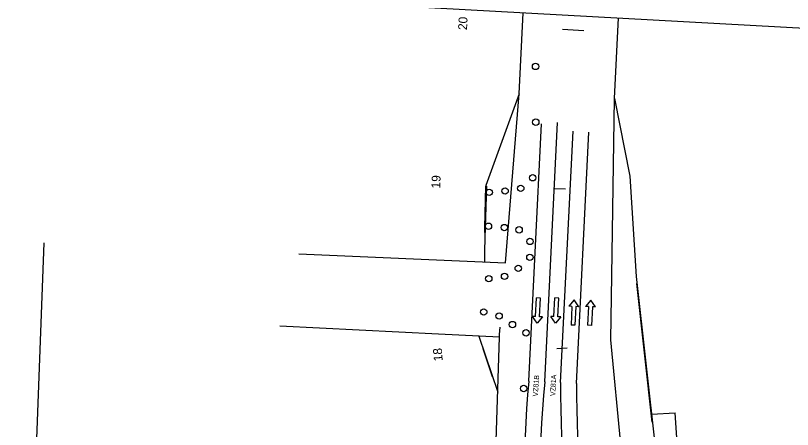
# Model space of a CAD drawing. Extents: x 0 to 1361828, y 0 to 1470398.
# Drawn here: x 685888.8 to 686377.1, y 735099.3 to 735359.4 of the extents above; entities that cross this region are included whole.
import ezdxf

# ---------------------------------------------------------------- set-up
doc = ezdxf.new("R2010")
doc.units = 0
for name, color, linetype in [('$', 7, 'Continuous'), ('border All Plan 20-40 - Level 1', 7, 'Continuous'), ('MOT Stage 1', 7, 'Continuous'), ('MOT Stage 1 Lanes', 7, 'Continuous'), ('R_Horz Alg Station', 7, 'Continuous'), ('R_TYPE_A_CURB', 7, 'Continuous'), ('RW-EX', 7, 'Continuous'), ('RW-PR', 7, 'Continuous'), ('SIGNAL-PR$', 7, 'Continuous')]:
    doc.layers.add(name, color=color, linetype=linetype)

# ---------------------------------------------------------------- blocks, each defined once
blk = doc.blocks.new('BAREL_1801')
at = {"layer": 'MOT Stage 1'}
blk.add_circle((0, 0.01), 2.88, dxfattribs=at)
blk = doc.blocks.new('BAREL_1802')
at = {"layer": 'MOT Stage 1'}
blk.add_circle((0, 0.01), 2.88, dxfattribs=at)
blk = doc.blocks.new('BAREL_1803')
at = {"layer": 'MOT Stage 1'}
blk.add_circle((0, 0.01), 2.88, dxfattribs=at)
blk = doc.blocks.new('BAREL_1804')
at = {"layer": 'MOT Stage 1'}
blk.add_circle((0, 0.01), 2.88, dxfattribs=at)
blk = doc.blocks.new('BAREL_1805')
at = {"layer": 'MOT Stage 1'}
blk.add_circle((0, 0.01), 2.88, dxfattribs=at)
blk = doc.blocks.new('BAREL_1806')
at = {"layer": 'MOT Stage 1'}
blk.add_circle((0, 0.01), 2.88, dxfattribs=at)
blk = doc.blocks.new('BAREL_1842')
at = {"layer": 'MOT Stage 1'}
blk.add_circle((0, 0.01), 2.88, dxfattribs=at)
blk = doc.blocks.new('BAREL_1843')
at = {"layer": 'MOT Stage 1'}
blk.add_circle((0, 0.01), 2.88, dxfattribs=at)
blk = doc.blocks.new('BAREL_1844')
at = {"layer": 'MOT Stage 1'}
blk.add_circle((0, 0.01), 2.88, dxfattribs=at)
blk = doc.blocks.new('BAREL_1845')
at = {"layer": 'MOT Stage 1'}
blk.add_circle((0, 0.01), 2.88, dxfattribs=at)
blk = doc.blocks.new('BAREL_1846')
at = {"layer": 'MOT Stage 1'}
blk.add_circle((0, 0.01), 2.88, dxfattribs=at)
blk = doc.blocks.new('BAREL_1847')
at = {"layer": 'MOT Stage 1'}
blk.add_circle((0, 0.01), 2.88, dxfattribs=at)
blk = doc.blocks.new('BAREL_1848')
at = {"layer": 'MOT Stage 1'}
blk.add_circle((0, 0.01), 2.88, dxfattribs=at)
blk = doc.blocks.new('BAREL_1849')
at = {"layer": 'MOT Stage 1'}
blk.add_circle((0, 0.01), 2.88, dxfattribs=at)
blk = doc.blocks.new('BAREL_1850')
at = {"layer": 'MOT Stage 1'}
blk.add_circle((0, 0.01), 2.88, dxfattribs=at)
blk = doc.blocks.new('BAREL_1851')
at = {"layer": 'MOT Stage 1'}
blk.add_circle((0, 0.01), 2.88, dxfattribs=at)
blk = doc.blocks.new('BAREL_1852')
at = {"layer": 'MOT Stage 1'}
blk.add_circle((0, 0.01), 2.88, dxfattribs=at)
blk = doc.blocks.new('SARROW_225')
at = {"layer": 'MOT Stage 1'}
for p, q in [((-6, -29.4), (-6, 0)), ((0, 0), (-6, 0)), ((0, -29.4), (0, 0)), ((-6, -29.4), (-11, -29.4)), ((-3, -39.8), (-11, -29.4)), ((5, -29.4), (-3, -39.8)), ((5, -29.4), (0, -29.4))]:
    blk.add_line(p, q, dxfattribs=at)
blk = doc.blocks.new('SARROW_226')
at = {"layer": 'MOT Stage 1'}
for p, q in [((-6, -29.4), (-6, 0)), ((0, 0), (-6, 0)), ((0, -29.4), (0, 0)), ((-6, -29.4), (-11, -29.4)), ((-3, -39.8), (-11, -29.4)), ((5, -29.4), (-3, -39.8)), ((5, -29.4), (0, -29.4))]:
    blk.add_line(p, q, dxfattribs=at)
blk = doc.blocks.new('SARROW_227')
at = {"layer": 'MOT Stage 1'}
for p, q in [((-6, -29.4), (-6, 0)), ((0, 0), (-6, 0)), ((0, -29.4), (0, 0)), ((-6, -29.4), (-11, -29.4)), ((-3, -39.8), (-11, -29.4)), ((5, -29.4), (-3, -39.8)), ((5, -29.4), (0, -29.4))]:
    blk.add_line(p, q, dxfattribs=at)
blk = doc.blocks.new('BAREL_1870')
at = {"layer": 'MOT Stage 1'}
blk.add_circle((0, 0.01), 2.88, dxfattribs=at)
blk = doc.blocks.new('BAREL_1871')
at = {"layer": 'MOT Stage 1'}
blk.add_circle((0, 0.01), 2.88, dxfattribs=at)
blk = doc.blocks.new('SARROW_228')
at = {"layer": 'MOT Stage 1'}
for p, q in [((-6, -29.4), (-6, 0)), ((0, 0), (-6, 0)), ((0, -29.4), (0, 0)), ((-6, -29.4), (-11, -29.4)), ((-3, -39.8), (-11, -29.4)), ((5, -29.4), (-3, -39.8)), ((5, -29.4), (0, -29.4))]:
    blk.add_line(p, q, dxfattribs=at)

msp = doc.modelspace()

# ---------------------------------------------------------------- linework, layer by layer
at = {"layer": 'border All Plan 20-40 - Level 1'}
msp.add_line((685446.82, 735403.36), (687025.3, 735315.9), dxfattribs=at)
at = {"layer": 'MOT Stage 1 Lanes'}
for points in [[(686221.44, 735129.26), (686229.44, 735292.13)], [(686211.45, 735129.75), (686219.39, 735291.41)], [(686231.42, 735128.77), (686239.18, 735286.65)], [(686241.41, 735128.27), (686249.17, 735286.16)]]:
    msp.add_lwpolyline(points, dxfattribs=at)
for centre, radius, start, end in [((686946.79, 735060.88), 738.56, 174.64944, 185.44699), ((686946.77, 735060.88), 728.55, 174.61469, 185.41281), ((686944.02, 735124.57), 712.61, 179.66251, 190.45935), ((686944, 735124.56), 702.6, 179.69727, 190.49468)]:
    msp.add_arc(centre, radius, start, end, dxfattribs=at)
at = {"layer": 'R_Horz Alg Station'}
for points in [[(686232.65, 735350.71), (686245.97, 735350.05)], [(686227.77, 735250.77), (686234.43, 735250.5)], [(686228.92, 735150.13), (686235.58, 735150.55)]]:
    msp.add_lwpolyline(points, dxfattribs=at)
at = {"layer": 'R_TYPE_A_CURB'}
for p, q in [((686184.46, 735252.11), (686184.96, 735252.1)), ((686183.73, 735223.02), (686184.23, 735223.01))]:
    msp.add_line(p, q, dxfattribs=at)
for points in [[(686183.73, 735223.02), (686183.74, 735226.25), (686184.46, 735252.11)], [(686184.23, 735223.01), (686184.24, 735226.24), (686184.96, 735252.1)], [(686289.03, 735103.92), (686279.27, 735191.01)], [(686188.63, 735132.43), (686182.76, 735149.94)]]:
    msp.add_lwpolyline(points, dxfattribs=at)
at = {"layer": 'RW-EX'}
for p, q in [((685894.65, 734899.71), (685906.88, 735216.51)), ((686066.93, 735209.73), (686196.68, 735203.99)), ((686282.11, 734952.68), (686263.01, 735155.56))]:
    msp.add_line(p, q, dxfattribs=at)
for points in [[(686196.68, 735203.99), (686205.39, 735310.21), (686207.85, 735361.16)], [(686263.01, 735155.56), (686263.62, 735196.09), (686265.32, 735307.32), (686267.76, 735357.83)], [(686193.04, 735157.41), (686154.73, 735159.27), (686054.94, 735164.12)], [(686189.41, 735046.56), (686193.04, 735157.41), (686193.09, 735158.93), (686193.31, 735163.53)]]:
    msp.add_lwpolyline(points, dxfattribs=at)
at = {"layer": 'RW-PR'}
for p, q in [((686180.05, 735158.04), (686191.9, 735122.66)), ((686288.47, 735108.89), (686303.36, 735109.86)), ((686306.92, 735054.97), (686303.36, 735109.86))]:
    msp.add_line(p, q, dxfattribs=at)
for points in [[(686205.39, 735310.21), (686184.48, 735252.55), (686183.74, 735226.25), (686183.66, 735204.57)], [(686265.32, 735307.32), (686274.84, 735258.53), (686278.78, 735195.38), (686290.99, 735086.46), (686300.18, 735004.43), (686311.76, 734922.2), (686343.56, 734897.83)]]:
    msp.add_lwpolyline(points, dxfattribs=at)

# ---------------------------------------------------------------- block references
at = {"layer": 'MOT Stage 1'}
for name, p, xscale, yscale, rotation in [('BAREL_1871', (686215.66, 735327.39), 0.6945420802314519, 0.6945420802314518, 87.04179557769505), ('BAREL_1870', (686215.8, 735292.39), 0.6945420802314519, 0.6945420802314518, 87.04179557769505), ('BAREL_1852', (686213.86, 735257.45), 0.6945420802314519, 0.6945420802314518, 87.04179557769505), ('BAREL_1851', (686206.34, 735250.85), 0.6945420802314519, 0.6945420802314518, 87.04179557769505), ('BAREL_1803', (686186.53, 735248.3), 0.6945420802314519, 0.6945420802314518, 87.04179557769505), ('BAREL_1850', (686196.5, 735249.11), 0.6945420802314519, 0.6945420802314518, 87.04179557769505), ('BAREL_1804', (686186.07, 735226.99), 0.6945420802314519, 0.6945420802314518, 87.04179557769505), ('BAREL_1805', (686196.03, 735226.18), 0.6945420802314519, 0.6945420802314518, 87.04179557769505), ('BAREL_1806', (686205.33, 735224.75), 0.6945420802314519, 0.6945420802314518, 87.04179557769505), ('BAREL_1845', (686212.15, 735217.43), 0.6945420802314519, 0.6945420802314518, 87.04179557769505), ('BAREL_1846', (686212.07, 735207.43), 0.6945420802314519, 0.6945420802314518, 87.04179557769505), ('BAREL_1847', (686204.78, 735200.59), 0.6945420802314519, 0.6945420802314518, 87.04179557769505), ('BAREL_1849', (686186.27, 735194.04), 0.6945420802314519, 0.6945420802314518, 87.04179557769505), ('BAREL_1848', (686196.16, 735195.52), 0.6945420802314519, 0.6945420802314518, 87.04179557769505), ('SARROW_225', (686218.68, 735181.91), 0.4000000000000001, 0.4000000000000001, -2.7722917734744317), ('SARROW_228', (686230.18, 735181.91), 0.4000000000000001, 0.4000000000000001, -2.7722917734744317), ('SARROW_226', (686240.32, 735164.82), 0.39999999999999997, -0.4, -2.7722917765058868), ('SARROW_227', (686250.79, 735164.63), 0.39999999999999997, -0.4, -2.7722917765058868), ('BAREL_1802', (686183.09, 735173.12), 0.6945420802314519, 0.6945420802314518, 87.04179557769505), ('BAREL_1801', (686192.77, 735170.62), 0.6945420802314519, 0.6945420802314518, 87.04179557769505), ('BAREL_1844', (686201.13, 735165.23), 0.6945420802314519, 0.6945420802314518, 87.04179557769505), ('BAREL_1843', (686209.67, 735160.03), 0.6945420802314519, 0.6945420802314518, 87.04179557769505), ('BAREL_1842', (686208.22, 735125.06), 0.6945420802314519, 0.6945420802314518, 87.04179557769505)]:
    msp.add_blockref(name, p, dxfattribs=dict(at, xscale=xscale, yscale=yscale, rotation=rotation))

# ---------------------------------------------------------------- texts
at = {"layer": '$'}
for s, rotation, p in [('20', 87.1878, (686172.55, 735350.12)), ('19', 87.6561, (686155.71, 735250.63)), ('18', 93.6561, (686157.28, 735142.34))]:
    msp.add_text(s, height=5.6, rotation=rotation, dxfattribs=at).set_placement(p)
at = {"layer": 'SIGNAL-PR$'}
for s, rotation, p in [('VZ81B', 85.9401, (686217, 735119.93)), ('VZ81A', 87.1966, (686227.98, 735120.2))]:
    msp.add_text(s, height=3.2, rotation=rotation, dxfattribs=at).set_placement(p)

doc.saveas('drawing.dxf')
